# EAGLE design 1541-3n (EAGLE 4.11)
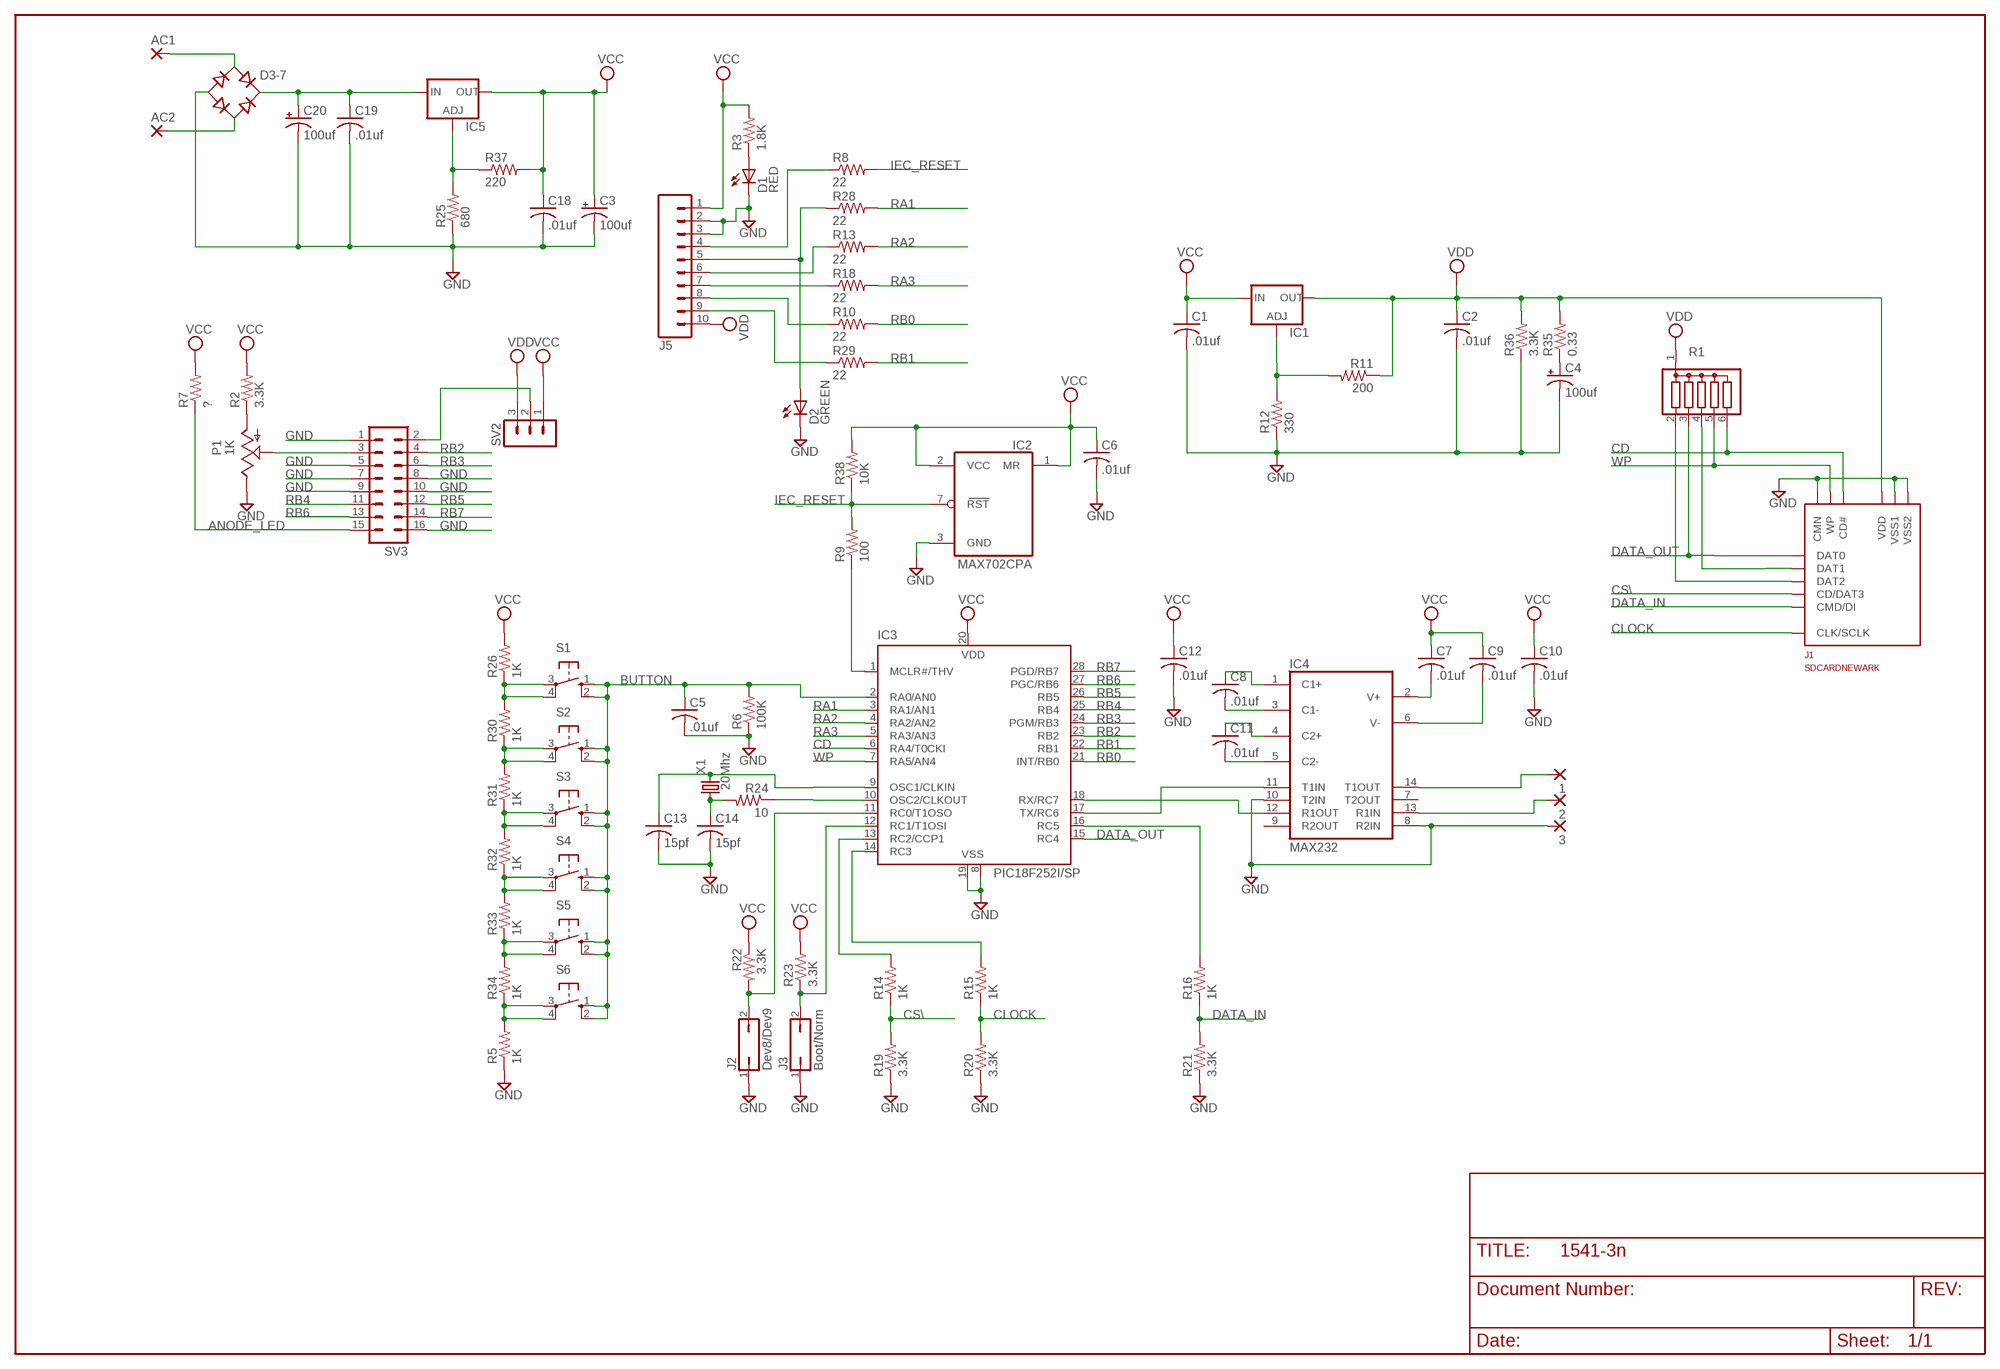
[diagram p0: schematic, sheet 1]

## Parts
1  2,15/1,0  [2,15/1,0]
2  2,15/1,0  [2,15/1,0]
3  2,15/1,0  [2,15/1,0]
AC1  2,15/1,0  [2,15/1,0]
AC2  2,15/1,0  [2,15/1,0]
C1  .01uf  C-US025-024X044  [C025-024X044]
C2  .01uf  C-US025-024X044  [C025-024X044]
C3  100uf  CPOL-USE2-5  [E2-5]
C4  100uf  CPOL-USE2-5  [E2-5]
C5  .01uf  C-US025-024X044  [C025-024X044]
C6  .01uf  C-US025-024X044  [C025-024X044]
C7  .01uf  C-US025-024X044  [C025-024X044]
C8  .01uf  C-US025-024X044  [C025-024X044]
C9  .01uf  C-US025-024X044  [C025-024X044]
C10  .01uf  C-US025-024X044  [C025-024X044]
C11  .01uf  C-US025-024X044  [C025-024X044]
C12  .01uf  C-US025-024X044  [C025-024X044]
C13  15pf  C-US025-024X044  [C025-024X044]
C14  15pf  C-US025-024X044  [C025-024X044]
C18  .01uf  C-US025-024X044  [C025-024X044]
C19  .01uf  C-US025-024X044  [C025-024X044]
C20  100uf  CPOL-USE2-5  [E2-5]
D1  RED  LED3MM  [LED3MM]
D2  GREEN  LED3MM  [LED3MM]
D3-7  RB1A  [RB1A]
IC1  LM317TS  [317TS]
IC2  MAX702CPA  [DIL08]
IC3  PIC18F252I/SP  PIC16F870P  [DIL28-3]
IC4  MAX232  [DIL16]
IC5  LM317TS  [317TS]
J1  SDCARDNEWARK  [SDBMF-00915B0T2]
J2  Dev8/Dev9  JP1Q  [JP1]
J3  Boot/Norm  JP1Q  [JP1]
J5  M10  [10P]
P1  1K  TRIM_US-LI10  [LI10]
R1  G05R  [SIL6]
R2  3.3K  R-US_0207/2V  [0207/2V]
R3  1.8K  R-US_0207/2V  [0207/2V]
R5  1K  R-US_0207/2V  [0207/2V]
R6  100K  R-US_0207/2V  [0207/2V]
R7  ?  R-US_0207/2V  [0207/2V]
R8  22  R-US_0207/2V  [0207/2V]
R9  100  R-US_0207/2V  [0207/2V]
R10  22  R-US_0207/2V  [0207/2V]
R11  200  R-US_0207/2V  [0207/2V]
R12  330  R-US_0207/2V  [0207/2V]
R13  22  R-US_0207/2V  [0207/2V]
R14  1K  R-US_0207/2V  [0207/2V]
R15  1K  R-US_0207/2V  [0207/2V]
R16  1K  R-US_0207/2V  [0207/2V]
R18  22  R-US_0207/2V  [0207/2V]
R19  3.3K  R-US_0207/2V  [0207/2V]
R20  3.3K  R-US_0207/2V  [0207/2V]
R21  3.3K  R-US_0207/2V  [0207/2V]
R22  3.3K  R-US_0207/2V  [0207/2V]
R23  3.3K  R-US_0207/2V  [0207/2V]
R24  10  R-US_0207/2V  [0207/2V]
R25  680  R-US_0207/2V  [0207/2V]
R26  1K  R-US_0207/2V  [0207/2V]
R28  22  R-US_0207/2V  [0207/2V]
R29  22  R-US_0207/2V  [0207/2V]
R30  1K  R-US_0207/2V  [0207/2V]
R31  1K  R-US_0207/2V  [0207/2V]
R32  1K  R-US_0207/2V  [0207/2V]
R33  1K  R-US_0207/2V  [0207/2V]
R34  1K  R-US_0207/2V  [0207/2V]
R35  0.33  R-US_0207/2V  [0207/2V]
R36  3.3K  R-US_0207/2V  [0207/2V]
R37  220  R-US_0207/2V  [0207/2V]
R38  10K  R-US_0207/2V  [0207/2V]
S1  10-XX  [B3F-10XX]
S2  10-XX  [B3F-10XX]
S3  10-XX  [B3F-10XX]
S4  10-XX  [B3F-10XX]
S5  10-XX  [B3F-10XX]
S6  10-XX  [B3F-10XX]
SV2  MA03-1  [MA03-1]
SV3  ML16  [ML16]
X1  20Mhz  CRYTALHC49U70  [HC49U70]

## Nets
ANODE_LED: R7.1 SV3.15
BUTTON: C5.1 IC3.2(RA0/AN0) R6.2 S1.1(S) S1.2(S1) S2.1(S) S2.2(S1) S3.1(S) S3.2(S1) S4.1(S) S4.2(S1) S5.1(S) S5.2(S1) S6.1(S) S6.2(S1)
CD: IC3.6(RA4/T0CKI) J1.SW1(CD#) R1.6
CLOCK: J1.CLK(CLK/SCLK) R15.1 R20.2
CS\: J1.DAT3(CD/DAT3) R14.1 R19.2
DATA_IN: J1.CMD(CMD/DI) R16.1 R21.2
DATA_OUT: IC3.15(RC4) J1.DAT0 R1.3
GND: 3.1(P) C1.2 C2.2 C3.- C4.- C5.2 C6.2 C10.2 C12.2 C13.2 C14.2 C18.2 C19.2 C20.- D1.K(C) D2.K(C) D3-7.- IC2.3(GND) IC3.8(VSS) IC3.19(VSS) IC4.8(R2IN) IC4.10(T2IN) J1.SW3(CMN) J1.VSS$1(VSS1) J1.VSS$2(VSS2) J2.1 J3.1 J5.2 J5.3 P1.E R5.1 R6.1 R12.1 R19.1 R20.1 R21.1 R25.1 R36.1 SV3.1 SV3.5 SV3.7 SV3.8 SV3.9 SV3.10 SV3.16
IEC_RESET: IC2.7(RST) R8.2 R9.2 R38.1
N$1: C4.+ R35.1
N$2: J1.DAT2 R1.2
N$3: J1.DAT1 R1.4
N$4: J5.9 R29.1
N$5: J5.8 R10.1
N$6: J5.7 R18.1
N$7: J5.4 R8.1
N$8: D2.A J5.5 R28.1
N$9: J5.6 R13.1
N$10: D1.A R3.1
N$11: IC3.18(RX/RC7) IC4.12(R1OUT)
N$12: IC3.14(RC3) R15.2
N$13: C14.1 R24.2 X1.1
N$14: IC3.1(MCLR#/THV) R9.1
N$15: C11.1 IC4.4(C2+)
N$16: C11.2 IC4.5(C2-)
N$17: C8.2 IC4.3(C1-)
N$18: C8.1 IC4.1(C1+)
N$19: C7.2 IC4.2(V+)
N$20: C13.1 IC3.9(OSC1/CLKIN) X1.2
N$21: IC3.10(OSC2/CLKOUT) R24.1
N$22: IC3.12(RC1/T1OSI) J3.2 R23.1
N$23: IC3.11(RC0/T1OSO) J2.2 R22.2
N$24: IC3.13(RC2/CCP1) R14.2
N$25: IC3.16(RC5) R16.2
N$26: IC1.1(ADJ) R11.2 R12.2
N$27: IC3.17(TX/RC6) IC4.11(T1IN)
N$28: R26.1 R30.2 S1.3(P) S1.4(P1)
N$29: R30.1 R31.2 S2.3(P) S2.4(P1)
N$30: R31.1 R32.2 S3.3(P) S3.4(P1)
N$31: R5.2 R34.1 S6.3(P) S6.4(P1)
N$32: R33.1 R34.2 S5.3(P) S5.4(P1)
N$33: R32.1 R33.2 S4.3(P) S4.4(P1)
N$34: P1.A R2.1
N$35: SV2.2 SV3.2
N$36: P1.S SV3.3
N$37: C9.2 IC4.6(V-)
N$38: IC5.1(ADJ) R25.2 R37.1
N$39: AC1.1(P) D3-7.AC1
N$40: C19.1 C20.+ D3-7.+ IC5.3(IN)
N$41: AC2.1(P) D3-7.AC2
N$42: 2.1(P) IC4.13(R1IN)
N$43: 1.1(P) IC4.14(T1OUT)
RA1: IC3.3(RA1/AN1) R28.2
RA2: IC3.4(RA2/AN2) R13.2
RA3: IC3.5(RA3/AN3) R18.2
RB0: IC3.21(INT/RB0) R10.2
RB1: IC3.22(RB1) R29.2
RB2: IC3.23(RB2) SV3.4
RB3: IC3.24(PGM/RB3) SV3.6
RB4: IC3.25(RB4) SV3.11
RB5: IC3.26(RB5) SV3.12
RB6: IC3.27(PGC/RB6) SV3.13
RB7: IC3.28(PGD/RB7) SV3.14
VCC: C1.1 C3.+ C6.1 C7.1 C9.1 C10.1 C12.1 C18.1 IC1.3(IN) IC2.1(MR) IC2.2(VCC) IC3.20(VDD) IC5.2(OUT) J5.1 R2.2 R3.2 R7.2 R22.1 R23.2 R26.2 R37.2 R38.2 SV2.1
VDD: C2.1 IC1.2(OUT) J1.VDD J5.10 R1.1 R11.1 R35.2 R36.2 SV2.3
WP: IC3.7(RA5/AN4) J1.SW2(WP) R1.5
Unconnected: IC4.7(T2OUT) IC4.9(R2OUT)

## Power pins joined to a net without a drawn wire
GND: IC4.15(GND) J1.GND$1(GND) J1.GND$5(GND)
VCC: IC4.16(VCC)

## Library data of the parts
1-3 AC1 AC2 = wirepad:2,15/1,0: THROUGH-HOLE PAD
C1 C2 C5-C14 C18 C19 = rcl:C-US: CAPACITOR, American symbol
C3 C4 C20 = rcl:CPOL-US: POLARIZED CAPACITOR, American symbol
D1 D2 = led:LED: LED
D3-7 = rectifier:RB1A: RECTIFIER 1 A
IC1 IC5 = v-reg:LM317TS: VOLTAGE REGULATOR
IC2 = maxim:MAX702CPA: POWER SUPPLY MONITOR
IC3 = microchip:PIC16*870: MICROCONTROLLER flash type
IC4 = maxim:MAX232: RS232 TRANSEIVER
J1 = sdcards:SDCARD: SD Card Holder
J2 J3 = jumper:JP1Q: JUMPER
J5 = con-amp-quick:M10: AMP QUICK CONNECTOR
P1 = pot:TRIM_US-: POTENTIOMETER
R1 = resistor-sil:G05R: SIL RESISTOR
R2 R3 R5-R16 R18-R26 R28-R38 = rcl:R-US_: RESISTOR, American symbol
S1-S6 = switch-omron:10-XX: OMRON SWITCH
SV2 = con-lstb:MA03-1: PIN HEADER
SV3 = con-harting-ml:ML16: HARTING
X1 = crystal:CRYTAL: CRYSTAL

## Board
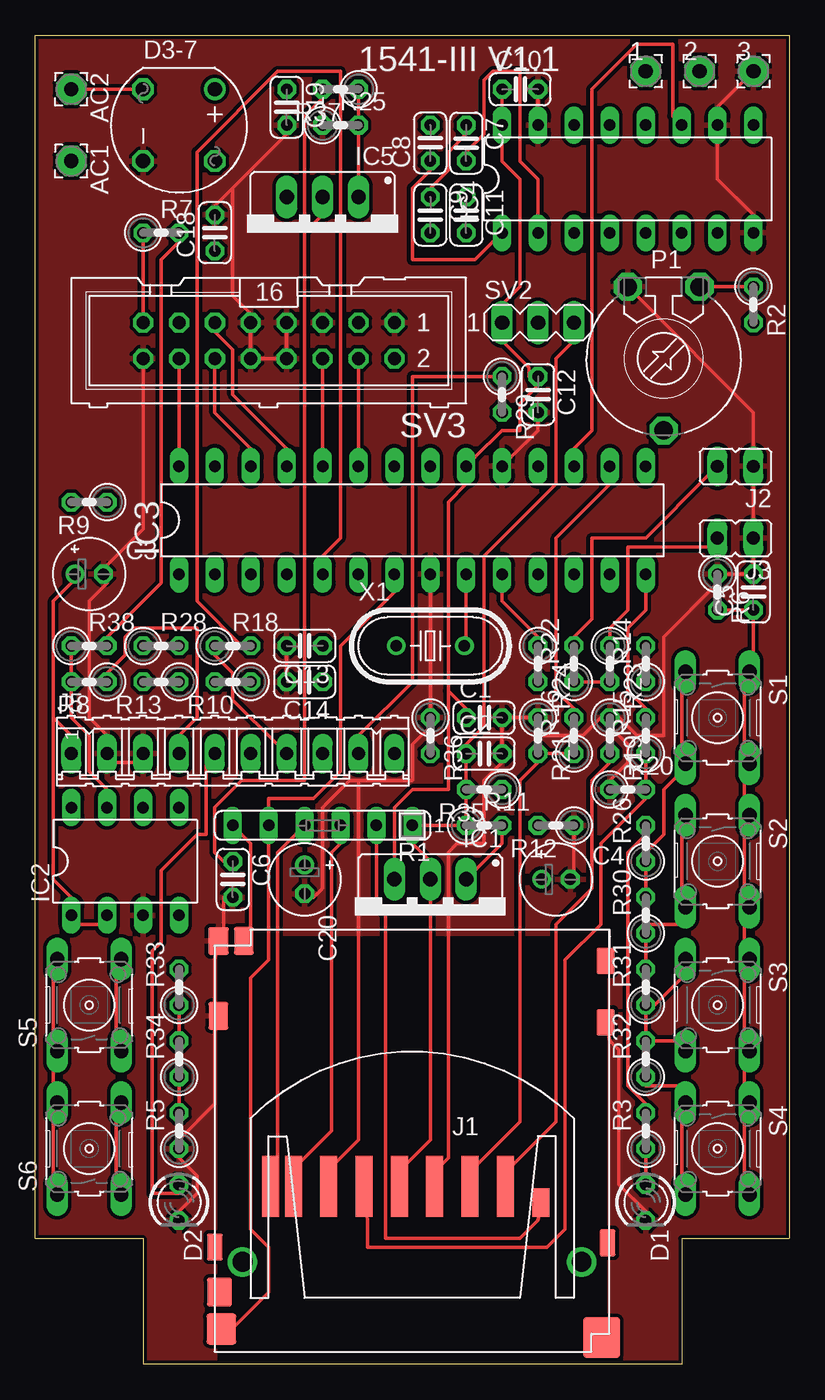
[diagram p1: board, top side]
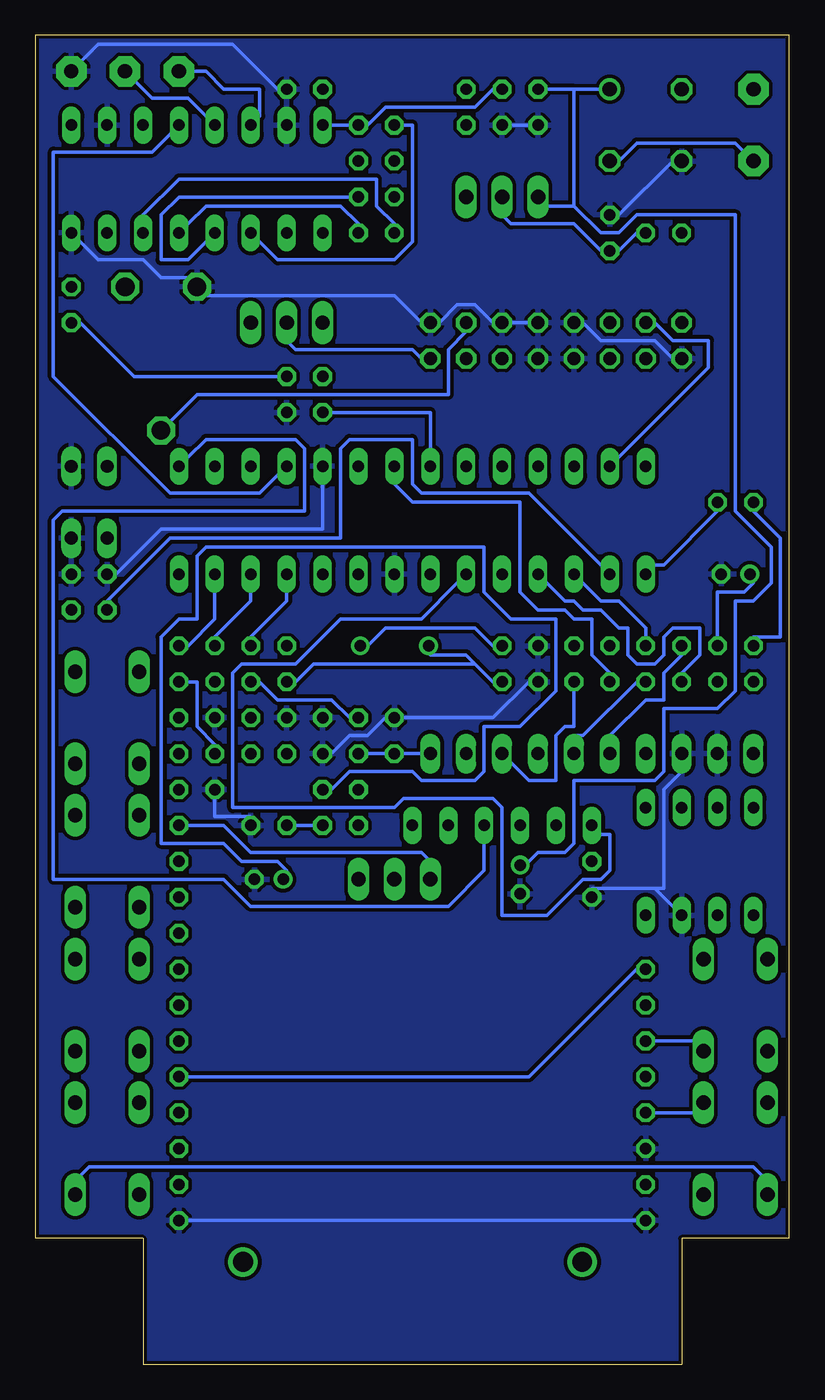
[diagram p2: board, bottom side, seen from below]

Size 53.34 x 93.98 mm. Coordinates in mm from the lower left corner, seen from the top.
Outline: 0,93.98 53.34,93.98 53.34,8.89 45.72,8.89 45.72,0 7.62,0 7.62,8.89 0,8.89 0,93.98
Copper layers (1*16): Top 0.035mm / dielectric 1.5mm / Bottom 0.035mm
Design rules "olimex10mil": minimum track width 10mil, minimum drill 24mil, track to track 10mil, track to pad 10mil, pad to pad 10mil, via to via 10mil, smd to smd 10mil, copper to edge 10mil, drill to drill 10mil, minimum pad ring 10mil, minimum via ring 8mil, stop-mask expansion 0mil, vias tented up to drill 0mil, thermal gap 10mil

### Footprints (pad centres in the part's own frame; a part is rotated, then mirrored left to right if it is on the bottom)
2,15/1,0 = drill 1.016 pad 2.159 octagon: 1 0,0
C025-024X044 = drill 0.813 octagon: 1 -1.27,0; 2 1.27,0
E2-5 = drill 0.813 pad 1.27 round: + -1.016,0 | drill 0.813 pad 1.27 octagon: - 1.016,0
LED3MM = drill 0.813 octagon: A -1.27,0; K 1.27,0
RB1A = drill 1.016 round: + -2.54,2.54 | drill 1.016 octagon: - 2.54,-2.54; AC1 2.54,2.54; AC2 -2.54,-2.54
317TS = drill 1.016 long: 1 -2.54,-2.54; 2 0,-2.54; 3 2.54,-2.54
DIL08 = drill 0.813 long: 1 -3.81,-3.81; 2 -1.27,-3.81; 3 1.27,-3.81; 4 3.81,-3.81; 5 3.81,3.81; 6 1.27,3.81; 7 -1.27,3.81; 8 -3.81,3.81
DIL28-3 = drill 0.813 long: 1 -16.51,-3.81; 2 -13.97,-3.81; 3 -11.43,-3.81; 4 -8.89,-3.81; 5 -6.35,-3.81; 6 -3.81,-3.81; 7 -1.27,-3.81; 8 1.27,-3.81; 9 3.81,-3.81; 10 6.35,-3.81; 11 8.89,-3.81; 12 11.43,-3.81; 13 13.97,-3.81; 14 16.51,-3.81; 15 16.51,3.81; 16 13.97,3.81; 17 11.43,3.81; 18 8.89,3.81; 19 6.35,3.81; 20 3.81,3.81; 21 1.27,3.81; 22 -1.27,3.81; 23 -3.81,3.81; 24 -6.35,3.81; 25 -8.89,3.81; 26 -11.43,3.81; 27 -13.97,3.81; 28 -16.51,3.81
DIL16 = drill 0.813 long: 1 -8.89,-3.81; 2 -6.35,-3.81; 3 -3.81,-3.81; 4 -1.27,-3.81; 5 1.27,-3.81; 6 3.81,-3.81; 7 6.35,-3.81; 8 8.89,-3.81; 9 8.89,3.81; 10 6.35,3.81; 11 3.81,3.81; 12 1.27,3.81; 13 -1.27,3.81; 14 -3.81,3.81; 15 -6.35,3.81; 16 -8.89,3.81
SDBMF-00915B0T2 = smd 1.2 x 4.3: CLK 3.1,-1.14; CMD -4.4,-1.14; DAT0 8.1,-1.14; DAT1 9.725,-1.14; DAT3 -6.9,-1.14; VDD 0.6,-1.14; VSS$1 -1.9,-1.14; VSS$2 5.6,-1.14 | smd 1.2 x 2: DAT2 -9.4,0.01 | smd 1.4 x 1.95: GND$1 13.4,-13.2; SW1 11.6,-18.5 | smd 1.143 x 1.905: GND$2 13.654,3.15; GND$6 -14.127,2.85 | smd 1.778 x 2.032: GND$3 13.327,6.327 | smd 1.3 x 1.9: GND$4 -14,-17.1; GND$5 -14,-12.75 | smd 2.6 x 2.9: GND$7 -13.7,9.55 | drill 1.4 pad 1.5 round: GND$8 11.7,4.2; GND$9 -12.3,4.2 | smd 2.1 x 2.2: SW2 13.2,8.95 | smd 1.45 x 1.95: SW3 13.4,-18.5
JP1 = drill 0.914 long: 1 0,-1.27; 2 0,1.27
10P = drill 0.914 long: 1 -11.43,0; 2 -8.89,0; 3 -6.35,0; 4 -3.81,0; 5 -1.27,0; 6 1.27,0; 7 3.81,0; 8 6.35,0; 9 8.89,0; 10 11.43,0
LI10 = drill 1.321 octagon: A -2.54,-5.08; E 2.54,-5.08; S 0,5.08
SIL6 = drill 0.813 long: 1 -6.35,0; 2 -3.81,0; 3 -1.27,0; 4 1.27,0; 5 3.81,0; 6 6.35,0
0207/2V = drill 0.813 octagon: 1 -1.27,0; 2 1.27,0
B3F-10XX = drill 1.016 long: 1 -3.251,2.261; 2 3.251,2.261; 3 -3.251,-2.261; 4 3.251,-2.261
MA03-1 = drill 1.016 long: 1 -2.54,0; 2 0,0; 3 2.54,0
ML16 = drill 0.914 octagon: 1 -8.89,-1.27; 2 -8.89,1.27; 3 -6.35,-1.27; 4 -6.35,1.27; 5 -3.81,-1.27; 6 -3.81,1.27; 7 -1.27,-1.27; 8 -1.27,1.27; 9 1.27,-1.27; 10 1.27,1.27; 11 3.81,-1.27; 12 3.81,1.27; 13 6.35,-1.27; 14 6.35,1.27; 15 8.89,-1.27; 16 8.89,1.27
HC49U70 = drill 0.813 round: 1 -2.413,0; 2 2.413,0

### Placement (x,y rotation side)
1  43.18,91.44 0 top
2  46.99,91.44 0 top
3  50.8,91.44 0 top
AC1  2.54,85.09 270 top
AC2  2.54,90.17 270 top
C1  31.75,45.72 0 top
C2  31.75,43.18 0 top
C3  3.81,55.88 0 top
C4  36.83,34.29 0 top
C5  50.8,54.61 90 top
C6  13.97,34.29 270 top
C7  30.48,86.36 270 top
C8  27.94,86.36 90 top
C9  27.94,81.28 270 top
C10  34.29,90.17 0 top
C11  30.48,81.28 270 top
C12  35.56,68.58 270 top
C13  19.05,50.8 180 top
C14  19.05,48.26 180 top
C18  12.7,80.01 90 top
C19  17.78,88.9 270 top
C20  19.05,34.29 270 top
D1  43.18,11.43 270 top
D2  10.16,11.43 270 top
D3-7  10.16,87.63 270 top
IC1  27.94,31.75 180 top
IC2  6.35,35.56 0 top
IC3  26.67,59.69 0 top
IC4  41.91,83.82 0 top
IC5  20.32,80.01 180 top
J1  26.35,11.43 180 top
J2  49.53,63.5 90 top
J3  49.53,58.42 90 top
J5  13.97,43.18 0 top
P1  44.45,71.12 180 top
R1  20.32,38.1 180 top
R2  50.8,74.93 270 top
R3  43.18,16.51 90 top
R5  10.16,16.51 90 top
R6  48.26,54.61 270 top
R7  8.89,80.01 0 top
R8  3.81,48.26 180 top
R9  3.81,60.96 180 top
R10  13.97,48.26 180 top
R11  31.75,38.1 0 top
R12  36.83,38.1 180 top
R13  8.89,48.26 180 top
R14  43.18,49.53 90 top
R15  43.18,44.45 90 top
R16  38.1,44.45 90 top
R18  13.97,50.8 0 top
R19  40.64,44.45 270 top
R20  41.91,40.64 0 top
R21  35.56,44.45 270 top
R22  38.1,49.53 90 top
R23  40.64,49.53 270 top
R24  35.56,49.53 270 top
R25  21.59,87.63 0 top
R26  43.18,36.83 90 top
R28  8.89,50.8 0 top
R29  33.02,68.58 270 top
R30  43.18,31.75 90 top
R31  43.18,26.67 90 top
R32  43.18,21.59 90 top
R33  10.16,26.67 90 top
R34  10.16,21.59 90 top
R35  31.75,40.64 180 top
R36  27.94,44.45 270 top
R37  21.59,90.17 180 top
R38  3.81,50.8 0 top
S1  48.26,45.72 270 top
S2  48.26,35.56 270 top
S3  48.26,25.4 270 top
S4  48.26,15.24 270 top
S5  3.81,25.4 90 top
S6  3.81,15.24 90 top
SV2  35.56,73.66 0 top
SV3  16.51,72.39 180 top
X1  27.94,50.8 0 top

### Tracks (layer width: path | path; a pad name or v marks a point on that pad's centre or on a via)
ANODE_LED
  Top 0.254: R7.1 7.62,79.38 7.62,74.3 SV3.15
BUTTON
  Top 0.254: R6.2 48.9,53.34 50.16,53.34 C5.1 50.8,52.7 50.8,50.16 S1.1 50.16,47.62 50.16,43.81 S1.2 50.16,41.27 50.16,40.01 S2.1 50.16,37.47 50.16,33.66 S2.2 50.16,31.11 50.16,29.84 S3.1 50.16,27.3 50.16,23.5 S3.2 50.16,20.95 50.16,19.68 S4.1 50.16,17.14 50.16,13.34 S4.2 | S6.1 1.27,13.34 1.27,17.14 S6.2 1.27,19.68 1.27,20.95 S5.1 1.27,23.5 1.27,27.3 S5.2
  Bottom 0.254: IC3.2 13.34,56.52 18.41,61.59 26.04,61.59 26.67,62.23 26.67,65.41 31.11,65.41 31.75,64.77 31.75,58.42 43.81,58.42 48.26,53.98 R6.2 | S6.1 1.91,13.34 2.54,13.97 49.53,13.97 50.16,13.34 S4.2
CD
  Top 0.254: J1.SW1 15.24,29.84 15.24,36.83 14.61,37.47 R1.6
  Bottom 0.254: IC3.6 23.5,55.24 26.04,52.7 31.75,52.7 34.92,49.53 38.73,49.53 39.37,48.9 39.37,39.37 27.94,39.37 27.3,40.01 20.95,40.01 20.32,39.37 20.32,31.75 17.14,31.75 14.61,34.29 13.34,34.29 12.7,34.92 12.7,37.47 13.34,37.47 R1.6
CLOCK
  Top 0.254: R15.1 43.18,42.55 43.18,41.27 R20.2 43.18,40.01 40.01,36.83 40.01,31.11 37.47,28.57 37.47,9.53 36.2,8.26 23.5,8.26 23.5,10.16 J1.CLK
CS\
  Top 0.254: J1.DAT3 33.66,13.97 36.83,17.14 36.83,31.11 39.37,33.66 39.37,41.27 40.64,42.55 R19.2
  Bottom 0.254: R19.2 40.64,43.81 41.91,45.09 41.91,48.26 42.55,48.26 R14.1
DATA_IN
  Top 0.254: R16.1 37.47,43.18 36.2,43.18 R21.2 35.56,42.55 34.29,41.27 34.29,17.14 31.11,13.97 J1.CMD
DATA_OUT
  Top 0.254: R1.3 21.59,36.83 20.95,36.2 20.95,16.51 18.41,13.97 J1.DAT0
  Bottom 0.254: IC3.15 42.55,64.14 41.27,65.41 34.92,65.41 34.29,64.77 34.29,60.33 51.44,60.33 52.07,59.69 52.07,34.29 40.01,34.29 38.1,32.38 24.13,32.38 21.59,34.92 21.59,36.83 R1.3
GND
  Top 0.254: J1.GND$5 40.64,22.86 41.27,22.23 41.27,12.7 43.18,10.79 D1.K | D2.K 10.16,10.79 11.43,12.06 11.43,13.34 10.16,14.61 R5.1 10.16,15.88 12.7,18.41 12.7,23.5 J1.GND$1 12.7,24.77 12.7,28.57 J1.SW3 13.34,29.84 13.34,33.02 C6.2 | J5.3 6.99,42.55 5.71,42.55 J5.2 5.08,44.45 3.81,45.72 3.81,53.98 5.08,55.24 C3.- 5.08,56.52 7.62,59.05 7.62,70.48 SV3.16 | C4.- 38.1,34.92 38.1,37.47 R12.1 | R19.1 40.64,45.09 41.91,43.81 41.91,42.55 40.64,41.27 R20.1 | J1.VSS$1 28.57,13.97 29.21,14.61 29.21,36.2 29.84,36.83 31.75,36.83 31.75,41.27 33.02,42.55 C2.2 33.02,43.81 33.02,45.09 C1.2 33.66,45.72 34.92,45.72 R21.1 35.56,45.09 35.56,44.45 38.73,44.45 40.01,45.72 R19.1 | C14.2 17.78,48.9 17.78,50.16 C13.2 | 22.86,41.27 26.67,41.27 26.67,43.81 27.94,45.09 R36.1 27.94,46.35 27.94,54.61 IC3.8 | 22.86,41.27 22.23,41.27 20.32,39.37 20.32,33.66 19.68,33.02 C20.- | 22.86,41.27 22.86,15.88 20.95,13.97 J1.VSS$2 | SV3.7 17.78,73.03 17.78,71.75 SV3.8 17.14,71.12 15.88,71.12 SV3.10 15.24,71.75 15.24,73.03 SV3.9 15.24,74.3 13.97,75.56 13.97,83.19 | 13.97,83.19 12.7,81.92 C18.2 | 13.97,83.19 17.78,87 C19.2 | IC4.15 35.56,88.9 35.56,89.53 C10.2 | 3.1 50.16,90.81 48.26,88.9 IC4.10 48.26,86.36 48.26,83.82 50.8,81.28 IC4.8 | IC3.19 33.66,64.14 35.56,66.04 35.56,66.67 C12.2 | P1.E 42.55,75.56 50.8,67.31 50.8,64.77 J2.1 50.8,62.23 50.8,59.69 J3.1 50.8,57.15 50.8,56.52 C5.2 50.16,55.88 48.9,55.88 R6.1 48.26,55.24 44.45,51.44 44.45,44.45 42.55,44.45 41.27,45.72 R19.1
  Bottom 0.254: 9.53,33.66 8.26,32.38 IC2.3 | 9.53,33.66 13.97,33.66 C6.2 | 9.53,33.66 8.89,33.66 8.89,40.64 7.62,41.91 J5.3 | D1.K 42.55,10.16 10.79,10.16 D2.K | R20.1 40.64,40.01 40.64,38.73 38.1,38.73 R12.1 | C14.2 18.41,48.26 20.95,45.72 27.3,45.72 R36.1 28.57,45.72 29.84,44.45 31.11,44.45 32.38,43.18 C2.2 | SV3.7 18.41,73.66 19.68,73.66 SV3.5 20.95,73.66 22.23,74.93 23.5,74.93 24.77,73.66 SV3.1 26.04,73.66 27.94,75.56 41.27,75.56 P1.E 42.55,76.83 44.45,76.83 45.72,78.11 48.9,78.11 50.16,79.38 IC4.8 | C19.2 18.41,87.63 19.68,87.63 R25.1 | C18.2 12.06,81.28 8.26,85.09 D3-7.- | SV3.16 8.26,71.12 9.53,72.39 13.34,72.39 14.61,73.66 SV3.9 | C10.2 36.2,90.17 39.37,93.34 48.9,93.34 50.16,92.08 3.1 | IC3.19 33.02,62.23 33.02,59.05 44.45,59.05 47.62,55.88 R6.1
  pour Bottom: 0,0 53.34,0 53.34,93.98 0,93.98
  pour Top: 0,0 12.7,0 12.7,30.48 40.64,30.48 40.64,0 53.34,0 53.34,93.98 0,93.98
IEC_RESET
  Top 0.254: R38.1 2.54,50.16 2.54,48.9 R8.2 2.54,47.62 2.54,45.72 3.81,44.45 3.81,41.91 5.08,40.64 IC2.7
  Bottom 0.254: R9.2 2.54,60.33 0.64,58.42 0.64,51.44 2.54,51.44 R38.1
N$1
  Bottom 0.254: R35.1 32.38,40.64 31.11,41.91 26.67,41.91 26.04,41.27 22.23,41.27 21.59,41.91 21.59,45.09 19.05,45.09 16.51,47.62 16.51,52.7 19.68,52.7 21.59,54.61 21.59,57.78 41.27,57.78 41.91,57.15 41.91,52.7 43.18,52.7 44.45,51.44 44.45,36.83 40.01,36.83 38.73,35.56 36.2,35.56 35.56,34.92 C4.+
N$2
  Top 0.254: J1.DAT2 35.56,10.16 34.29,8.89 24.77,8.89 24.77,31.75 24.13,32.38 24.13,36.83 R1.2
N$3
  Top 0.254: R1.4 18.41,37.47 17.14,36.2 17.14,13.97 J1.DAT1
N$4
  Top 0.254: R29.1 32.38,69.85 26.67,69.85 26.67,48.26 22.86,44.45 J5.9
N$5
  Bottom 0.254: R10.1 15.24,47.62 15.24,45.09 15.88,45.09 16.51,44.45 16.51,41.27 18.41,41.27 19.68,42.55 J5.8
N$6
  Top 0.254: R18.1 12.7,50.16 13.97,48.9 13.97,46.99 17.14,43.81 J5.7
N$7
  Top 0.254: R8.1 5.08,48.9 6.35,50.16 6.35,51.44 6.99,52.07 11.43,52.07 11.43,45.72 10.16,44.45 J5.4
N$8
  Top 0.254: D2.A 10.16,12.06 8.26,12.06 8.26,29.21 8.89,29.84 8.89,34.92 11.43,37.47 12.06,37.47 12.06,42.55 J5.5
  Bottom 0.254: R28.1 7.62,50.16 8.89,48.9 8.89,46.99 10.16,46.99 12.7,44.45 J5.5
N$9
  Bottom 0.254: R13.1 10.79,48.26 14.61,44.45 15.24,44.45 J5.6
N$10
  Top 0.254: D1.A 43.18,13.34 43.18,14.61 R3.1
N$11
  Bottom 0.254: IC3.18 36.2,62.87 37.47,61.59 43.81,61.59 52.07,69.85 52.07,85.72 45.09,85.72 43.81,87 IC4.12
N$12
  Top 0.254: R15.2 43.18,46.35 41.91,47.62 41.91,52.07 43.18,53.34 43.18,54.61 IC3.14
N$13
  Bottom 0.254: 22.23,49.53 22.86,50.16 25.4,50.16 X1.1 | 22.23,49.53 20.95,48.26 C14.1 | 22.23,49.53 33.66,49.53 34.92,48.26 R24.2
N$14
  Bottom 0.254: R9.1 5.08,60.33 8.89,56.52 9.53,56.52 IC3.1
N$15
  Bottom 0.254: C11.1 31.11,82.55 43.18,82.55 44.45,81.28 44.45,78.11 42.55,78.11 41.27,79.38 IC4.4
N$16
  Bottom 0.254: C11.2 30.48,80.64 31.75,81.92 41.27,81.92 42.55,80.64 IC4.5
N$17
  Bottom 0.254: IC4.3 37.47,79.38 36.2,78.11 27.94,78.11 26.67,79.38 26.67,87.63 27.3,87.63 C8.2
N$18
  Top 0.254: IC4.1 32.38,79.38 31.11,78.11 26.67,78.11 26.67,83.19 27.94,84.45 C8.1
N$19
  Top 0.254: C7.2 30.48,85.72 31.75,87 31.75,90.81 32.38,91.44 34.29,91.44 34.29,85.09 35.56,83.82 35.56,81.28 IC4.2
N$20
  Top 0.254: IC3.9 30.48,54.61 30.48,51.44 X1.2
  Bottom 0.254: C13.1 20.95,50.8 22.23,52.07 28.57,52.07 29.84,50.8 X1.2
N$21
  Top 0.254: R24.1 35.56,51.44 33.02,53.98 33.02,54.61 IC3.10
N$22
  Top 0.254: J3.2 47.62,57.78 41.91,57.78 41.91,53.34 40.64,52.07 40.64,51.44 R23.1
  Bottom 0.254: R23.1 40.64,51.44 38.1,53.98 38.1,54.61 IC3.12
N$23
  Top 0.254: J2.2 47.62,62.87 43.18,58.42 39.37,58.42 39.37,52.7 38.1,51.44 R22.2
  Bottom 0.254: R22.2 38.1,51.44 35.56,53.98 35.56,54.61 IC3.11
N$24
  Bottom 0.254: R14.2 42.55,50.8 40.64,52.7 40.64,54.61 IC3.13
N$25
  Top 0.254: R16.2 38.1,46.35 36.83,47.62 36.83,58.42 40.64,62.23 IC3.16
N$26
  Top 0.254: IC1.1 31.11,34.92 33.02,36.83 33.02,37.47 R11.2
  Bottom 0.254: R11.2 33.66,38.1 34.92,38.1 R12.2
N$27
  Top 0.254: IC3.17 38.1,64.77 39.37,66.04 39.37,90.17 42.55,93.34 45.09,93.34 45.09,88.27 IC4.11
N$28
  Top 0.254: R30.2 43.18,33.66 43.18,34.92 R26.1 43.18,36.2 44.45,37.47 44.45,40.64 45.72,41.91 S1.4 45.72,43.81 45.72,47.62 S1.3
N$29
  Top 0.254: R31.2 43.18,28.57 43.18,29.84 R30.1 43.18,31.11 45.72,31.11 S2.4 45.72,33.66 45.72,37.47 S2.3
N$30
  Top 0.254: S3.4 45.72,22.86 43.81,22.86 R32.2 43.18,23.5 43.18,24.77 R31.1 43.81,25.4 45.72,27.3 S3.3
N$31
  Top 0.254: R5.2 10.16,18.41 10.16,19.68 R34.1 | S6.3 5.71,13.34 5.71,17.14 S6.4
  Bottom 0.254: R5.2 9.53,17.78 6.35,17.78 S6.4
N$32
  Top 0.254: R34.2 10.16,23.5 10.16,24.77 R33.1 | S5.4 5.71,27.3 5.71,23.5 S5.3
  Bottom 0.254: S5.3 6.35,22.86 9.53,22.86 R34.2
N$33
  Top 0.254: S4.4 45.72,13.34 45.72,17.14 S4.3 45.72,19.68 43.18,19.68 R32.1
  Bottom 0.254: R33.2 10.79,27.94 18.41,20.32 42.55,20.32 R32.1
N$34
  Top 0.254: R2.1 50.16,76.2 47.62,76.2 P1.A
N$35
  Bottom 0.254: SV3.2 26.04,71.12 26.67,71.75 34.92,71.75 35.56,72.39 SV2.2
N$36
  Bottom 0.254: SV3.3 22.86,73.03 24.13,71.75 24.13,68.58 41.91,68.58 43.81,66.67 P1.S
N$37
  Bottom 0.254: C9.2 27.94,80.64 29.21,81.92 29.21,83.82 43.18,83.82 45.72,81.28 IC4.6
N$38
  Top 0.254: R37.1 22.86,89.53 22.86,88.27 R25.2 22.86,87 22.86,83.82 IC5.1
N$39
  Bottom 0.254: D3-7.AC1 12.06,85.09 10.79,86.36 3.81,86.36 3.17,85.72 AC1.1
N$40
  Bottom 0.254: 15.24,90.17 13.34,90.17 D3-7.+ | 15.24,90.17 17.14,90.17 C19.1 | 15.24,81.92 13.34,80.01 12.06,80.01 10.79,81.28 3.81,81.28 3.81,60.33 1.27,57.78 1.27,55.24 2.54,53.98 3.81,53.98 3.81,47.62 5.08,46.35 8.89,46.35 8.89,41.91 9.53,41.27 15.24,41.27 15.24,36.83 15.88,36.2 17.78,36.2 18.41,35.56 C20.+ | 15.24,81.92 17.14,81.92 IC5.3 | 15.24,81.92 15.24,90.17
N$41
  Top 0.254: D3-7.AC2 6.99,90.17 3.17,90.17 AC2.1
N$42
  Bottom 0.254: IC4.13 41.27,88.27 42.55,89.53 45.09,89.53 46.35,90.81 2.1
N$43
  Bottom 0.254: IC4.14 37.47,88.27 37.47,90.17 40.01,90.17 41.27,91.44 42.55,91.44 1.1
RA1
  Bottom 0.254: IC3.3 14.61,55.24 13.34,53.98 12.06,53.98 10.16,52.07 10.16,51.44 R28.2
RA2
  Bottom 0.254: R13.2 7.62,48.9 6.35,50.16 6.35,52.07 8.26,52.07 8.89,51.44 8.89,50.16 9.53,49.53 10.79,49.53 11.43,50.16 11.43,52.07 12.06,52.07 13.34,53.34 14.61,53.34 15.24,53.98 15.88,53.98 17.14,55.24 IC3.4
RA3
  Top 0.254: R18.2 14.61,50.8 11.43,53.98 11.43,85.72 17.14,91.44 21.59,91.44 21.59,58.42 20.32,57.15 IC3.5
RB0
  Bottom 0.254: R10.2 12.7,48.9 13.97,50.16 13.97,52.7 15.24,52.7 15.88,53.34 17.78,53.34 19.05,54.61 19.05,60.96 26.67,60.96 27.94,62.23 IC3.21
RB1
  Bottom 0.254: IC3.22 25.4,64.77 25.4,67.31 32.38,67.31 R29.2
RB2
  Top 0.254: IC3.23 22.86,64.77 22.86,70.48 SV3.4
RB3
  Top 0.254: IC3.24 20.32,64.77 20.32,70.48 SV3.6
RB4
  Top 0.254: IC3.25 17.78,64.77 13.97,68.58 13.97,71.75 12.7,73.03 SV3.11
RB5
  Top 0.254: IC3.26 15.24,64.77 12.7,67.31 12.7,70.48 SV3.12
RB6
  Bottom 0.254: IC3.27 12.06,64.14 5.71,70.48 5.71,72.39 8.26,72.39 9.53,73.66 SV3.13
RB7
  Top 0.254: IC3.28 10.16,64.77 10.16,70.48 SV3.14
VCC
  Top 0.254: R3.2 43.18,18.41 41.91,19.68 41.91,36.2 43.18,37.47 R26.2 | R23.2 40.01,48.26 38.73,48.26 R22.1 | 29.21,47.62 30.48,46.35 C1.1 | 29.21,47.62 29.21,60.96 30.48,62.23 IC3.20 31.11,64.14 33.02,66.04 34.29,66.04 34.29,67.94 35.56,69.22 C12.1 34.92,69.85 34.92,70.48 33.02,72.39 SV2.1 33.02,74.93 34.29,76.2 34.29,83.82 33.02,85.09 33.02,86.36 IC4.16 33.02,88.9 33.02,89.53 C10.1 | 29.21,47.62 29.21,40.64 26.67,40.64 25.4,39.37 25.4,35.56 IC1.3 | IC2.2 4.45,31.11 3.17,31.11 IC2.1 2.54,33.02 1.27,34.29 1.27,45.72 | 1.27,45.72 1.27,53.98 2.54,55.24 C3.+ | 1.27,45.72 2.54,44.45 J5.1 | C9.1 27.94,83.19 29.21,84.45 29.21,85.72 30.48,87 C7.1 | 19.05,80.01 19.05,41.27 14.61,41.27 12.7,39.37 12.7,36.2 13.34,35.56 C6.1 | 19.05,80.01 20.32,81.28 IC5.2 | 19.05,80.01 19.05,88.27 20.32,89.53 R37.2 | R38.2 5.08,51.44 8.89,55.24 8.89,78.11 10.16,79.38 R7.2
  Bottom 0.254: IC1.3 25.4,35.56 26.04,36.2 38.1,36.2 40.01,38.1 42.55,38.1 R26.2 | C1.1 31.11,45.72 32.38,46.99 36.2,46.99 37.47,48.26 R22.1 | R2.2 50.16,73.66 46.35,69.85 36.2,69.85 C12.1 | R38.2 5.08,51.44 5.08,54.61 3.17,54.61 2.54,55.24 C3.+ | IC4.16 32.38,87.63 31.11,87.63 C7.1 29.84,87.63 28.57,88.9 22.23,88.9 20.95,90.17 R37.2 | R7.2 10.79,80.01 12.06,78.74 C18.1 13.34,78.74 15.24,80.64 19.68,80.64 20.32,81.28 IC5.2
VDD
  Top 0.254: J1.VDD 26.04,13.97 27.94,15.88 27.94,33.02 IC1.2 27.94,35.56 26.67,36.83 R1.1 27.3,38.1 29.84,38.1 R11.1 30.48,38.73 30.48,40.01 R35.2 30.48,41.27 30.48,42.55 C2.1 30.48,43.81 31.75,45.09 31.75,57.15 36.83,62.23 36.83,71.12 38.1,72.39 SV2.3
  Bottom 0.254: J5.10 26.04,43.18 27.3,43.18 R36.2 28.57,43.18 29.84,43.18 C2.1
WP
  Top 0.254: J1.SW2 13.97,2.54 16.51,5.08 16.51,8.26 15.24,9.53 15.24,27.3 16.51,28.57 16.51,36.83 R1.5 16.51,39.37 16.51,40.01 19.68,40.01 21.59,41.91 21.59,50.8 25.4,54.61 IC3.7

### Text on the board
tPlace: 1541-III V1.1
